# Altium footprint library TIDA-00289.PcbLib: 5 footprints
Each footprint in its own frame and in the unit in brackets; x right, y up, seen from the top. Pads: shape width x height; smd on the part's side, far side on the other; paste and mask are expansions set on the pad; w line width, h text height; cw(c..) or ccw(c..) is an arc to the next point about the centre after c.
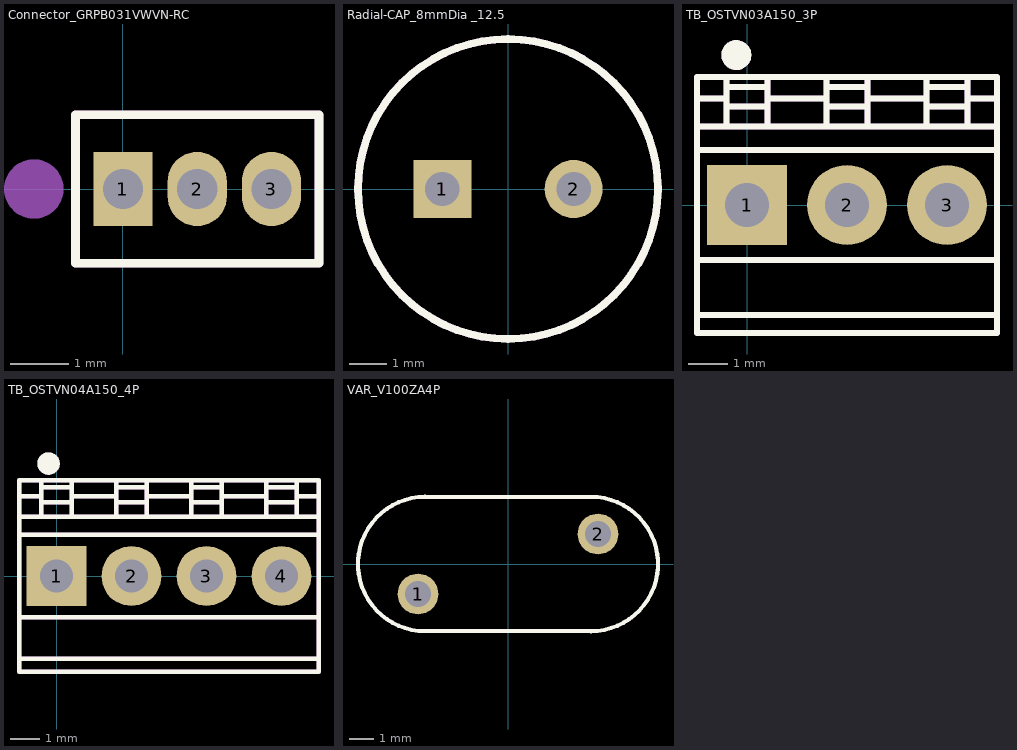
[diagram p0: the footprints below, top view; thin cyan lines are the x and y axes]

## Connector_GRPB031VWVN-RC [mil] "CONN HEADER .050\" 3POS PCB GOLD"
height 118
pads (3):
  rect 40x50 hole 27: 1(0,0)
  oval 40x50 hole 27: 2(50,0) 3(100,0)
Top Overlay:
  lines w6: -32,-50 132,-50 132,50 -32,50 -32,-50
Mechanical 5:
  circle w20: c-60,0 r10
  lines w6: -32,-50 -32,50 132,50 132,-50 -32,-50
  text ".Designator" at -160,75 h40
3D body: height 150, standoff 0, extent -32,-50 132,50

## Radial-CAP_8mmDia _12.5 [mil] "Radial, Can"
height 492.13
pads (2):
  rect 61x61 hole 36: 1(-68.9,0)
  round 61 hole 36: 2(68.9,0)
Top Overlay:
  circle w8: c0,0 r157.48
Mechanical 5:
  circle w7.87: c0,0 r157.48
  text ".Designator" at -185,75 h40
3D body: height 492.13, standoff 0, extent -156.23,-157.16 157.49,157.17

## TB_OSTVN03A150_3P [mil]
height 400
pads (3):
  rect 80x80 / inner round 80 / far side rect 80x80 hole 44: 1(0,0)
  round 80 hole 44: 2(100,0) 3(200,0)
Top Overlay:
  circle w10: c-10.63,149.95 r5
  circle w10: c-10.63,149.95 r10
  lines w6: -50,-110.24 250,-110.24 ; -50,-55.12 250,-55.12 ; -50,55.12 250,55.12 ; -50,78.74 250,78.74 ; -50,106.3 -20.87,106.3 ; -20.47,78.74 -20.47,127.95 ; -20.47,98.43 18.5,98.43 ; -20.47,118.11 18.5,118.11 ; 20.47,78.74 20.47,127.95 ; 22.44,106.3 77.56,106.3 ; 79.53,78.74 79.53,127.95 ; 81.5,98.43 116.93,98.43 ; 81.5,118.11 116.93,118.11 ; 120.47,78.74 120.47,127.95 ; 120.87,106.3 179.53,106.3 ; 179.53,78.74 179.53,127.95 ; 181.5,98.43 220.47,98.43 ; 181.5,118.11 220.47,118.11 ; 220.47,78.74 220.47,127.95 ; 220.87,106.3 250,106.3 ; -50,-127.95 -50,127.95 250,127.95 250,-127.95 -50,-127.95
Mechanical 5:
  circle w10: c-10.63,149.95 r10
  circle w10: c-10.63,149.95 r5
  lines w6: -50,-110.24 250,-110.24 ; -50,-55.12 250,-55.12 ; -50,55.12 250,55.12 ; -50,78.74 250,78.74 ; -50,106.3 -20.87,106.3 ; -20.47,78.74 -20.47,127.95 ; -20.47,98.43 18.5,98.43 ; -20.47,118.11 18.5,118.11 ; 20.47,78.74 20.47,127.95 ; 22.44,106.3 77.56,106.3 ; 79.53,78.74 79.53,127.95 ; 81.5,98.43 116.93,98.43 ; 81.5,118.11 116.93,118.11 ; 120.47,78.74 120.47,127.95 ; 120.87,106.3 179.53,106.3 ; 179.53,78.74 179.53,127.95 ; 181.5,98.43 220.47,98.43 ; 181.5,118.11 220.47,118.11 ; 220.47,78.74 220.47,127.95 ; 220.87,106.3 250,106.3 ; -50,-127.95 250,-127.95 250,127.95 -50,127.95 -50,-127.95
  text ".Designator" at 30,145 h40

## TB_OSTVN04A150_4P [mil]
height 400
pads (4):
  rect 80x80 / inner round 80 / far side rect 80x80 hole 44: 1(0,0)
  round 80 hole 44: 2(100,0) 3(200,0) 4(300,0)
Top Overlay:
  circle w10: c-10.63,149.95 r5
  circle w10: c-10.63,149.95 r10
  lines w6: -50,-110.24 350,-110.24 ; -50,-55.12 350,-55.12 ; -50,55.12 350,55.12 ; -50,78.74 350,78.74 ; -50,106.3 -20.87,106.3 ; -20.47,78.74 -20.47,127.95 ; -20.47,98.43 18.5,98.43 ; -20.47,118.11 18.5,118.11 ; 20.47,78.74 20.47,127.95 ; 22.44,106.3 77.56,106.3 ; 79.53,78.74 79.53,127.95 ; 81.5,98.43 116.93,98.43 ; 81.5,118.11 116.93,118.11 ; 120.47,78.74 120.47,127.95 ; 120.87,106.3 179.53,106.3 ; 179.53,78.74 179.53,127.95 ; 181.5,98.43 220.47,98.43 ; 181.5,118.11 220.47,118.11 ; 220.87,106.3 279.53,106.3 ; 279.53,78.74 279.53,127.95 ; 281.5,98.43 320.47,98.43 ; 281.5,118.11 320.47,118.11 ; 320.47,78.74 320.47,127.95 ; 320.87,106.3 350,106.3 ; -50,-127.95 -50,127.95 350,127.95 350,-127.95 -50,-127.95 ; 220.47,78.74 220.47,127.95 220.47,78.74
Mechanical 5:
  circle w10: c-10.63,149.95 r10
  circle w10: c-10.63,149.95 r5
  lines w6: -50,-110.24 350,-110.24 ; -50,-55.12 350,-55.12 ; -50,55.12 350,55.12 ; -50,78.74 350,78.74 ; -50,106.3 -20.87,106.3 ; -20.47,78.74 -20.47,127.95 ; -20.47,98.43 18.5,98.43 ; -20.47,118.11 18.5,118.11 ; 20.47,78.74 20.47,127.95 ; 22.44,106.3 77.56,106.3 ; 79.53,78.74 79.53,127.95 ; 81.5,98.43 116.93,98.43 ; 81.5,118.11 116.93,118.11 ; 120.47,78.74 120.47,127.95 ; 120.87,106.3 179.53,106.3 ; 179.53,78.74 179.53,127.95 ; 181.5,98.43 220.47,98.43 ; 181.5,118.11 220.47,118.11 ; 220.87,106.3 279.53,106.3 ; 279.53,78.74 279.53,127.95 ; 281.5,98.43 320.47,98.43 ; 281.5,118.11 320.47,118.11 ; 320.47,78.74 320.47,127.95 ; 320.87,106.3 350,106.3 ; 350,-127.95 -50,-127.95 -50,127.95 350,127.95 ; 350,-127.95 350,127.95 ; 350,-127.95 350,127.95 ; 220.47,78.74 220.47,127.95 220.47,78.74
  text ".Designator" at 35,180 h40

## VAR_V100ZA4P [mil] "VARISTOR  DISC 10MM"
height 629.92
pads (2):
  round 67 hole 42: 1(-147.64,-49.21) 2(147.64,49.21)
Top Overlay:
  lines w6.69: -140,-110 135.83,-110.29 ; -135.83,-110.24 cw(c-135.83,0) -135.83,110.24 ; -135.83,110.29 140,110 ; 135.83,-110.24 ccw(c135.83,0) 135.83,110.24
Mechanical 5:
  lines w3.94: -135.83,-110.24 cw(c-135.83,0) -135.83,110.24 135.83,110.24 cw(c135.83,0) 135.83,-110.24 -135.83,-110.24
  text ".Designator" at -160,-20 h40
3D body: height 275.59, standoff -118.11, extent 135.93,37.43 159.46,61.01
3D body: height 275.59, standoff -118.11, extent -161.71,-61.78 -138.18,-38.2
3D body: height 629.92, standoff 0, extent -245,-110 245,110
